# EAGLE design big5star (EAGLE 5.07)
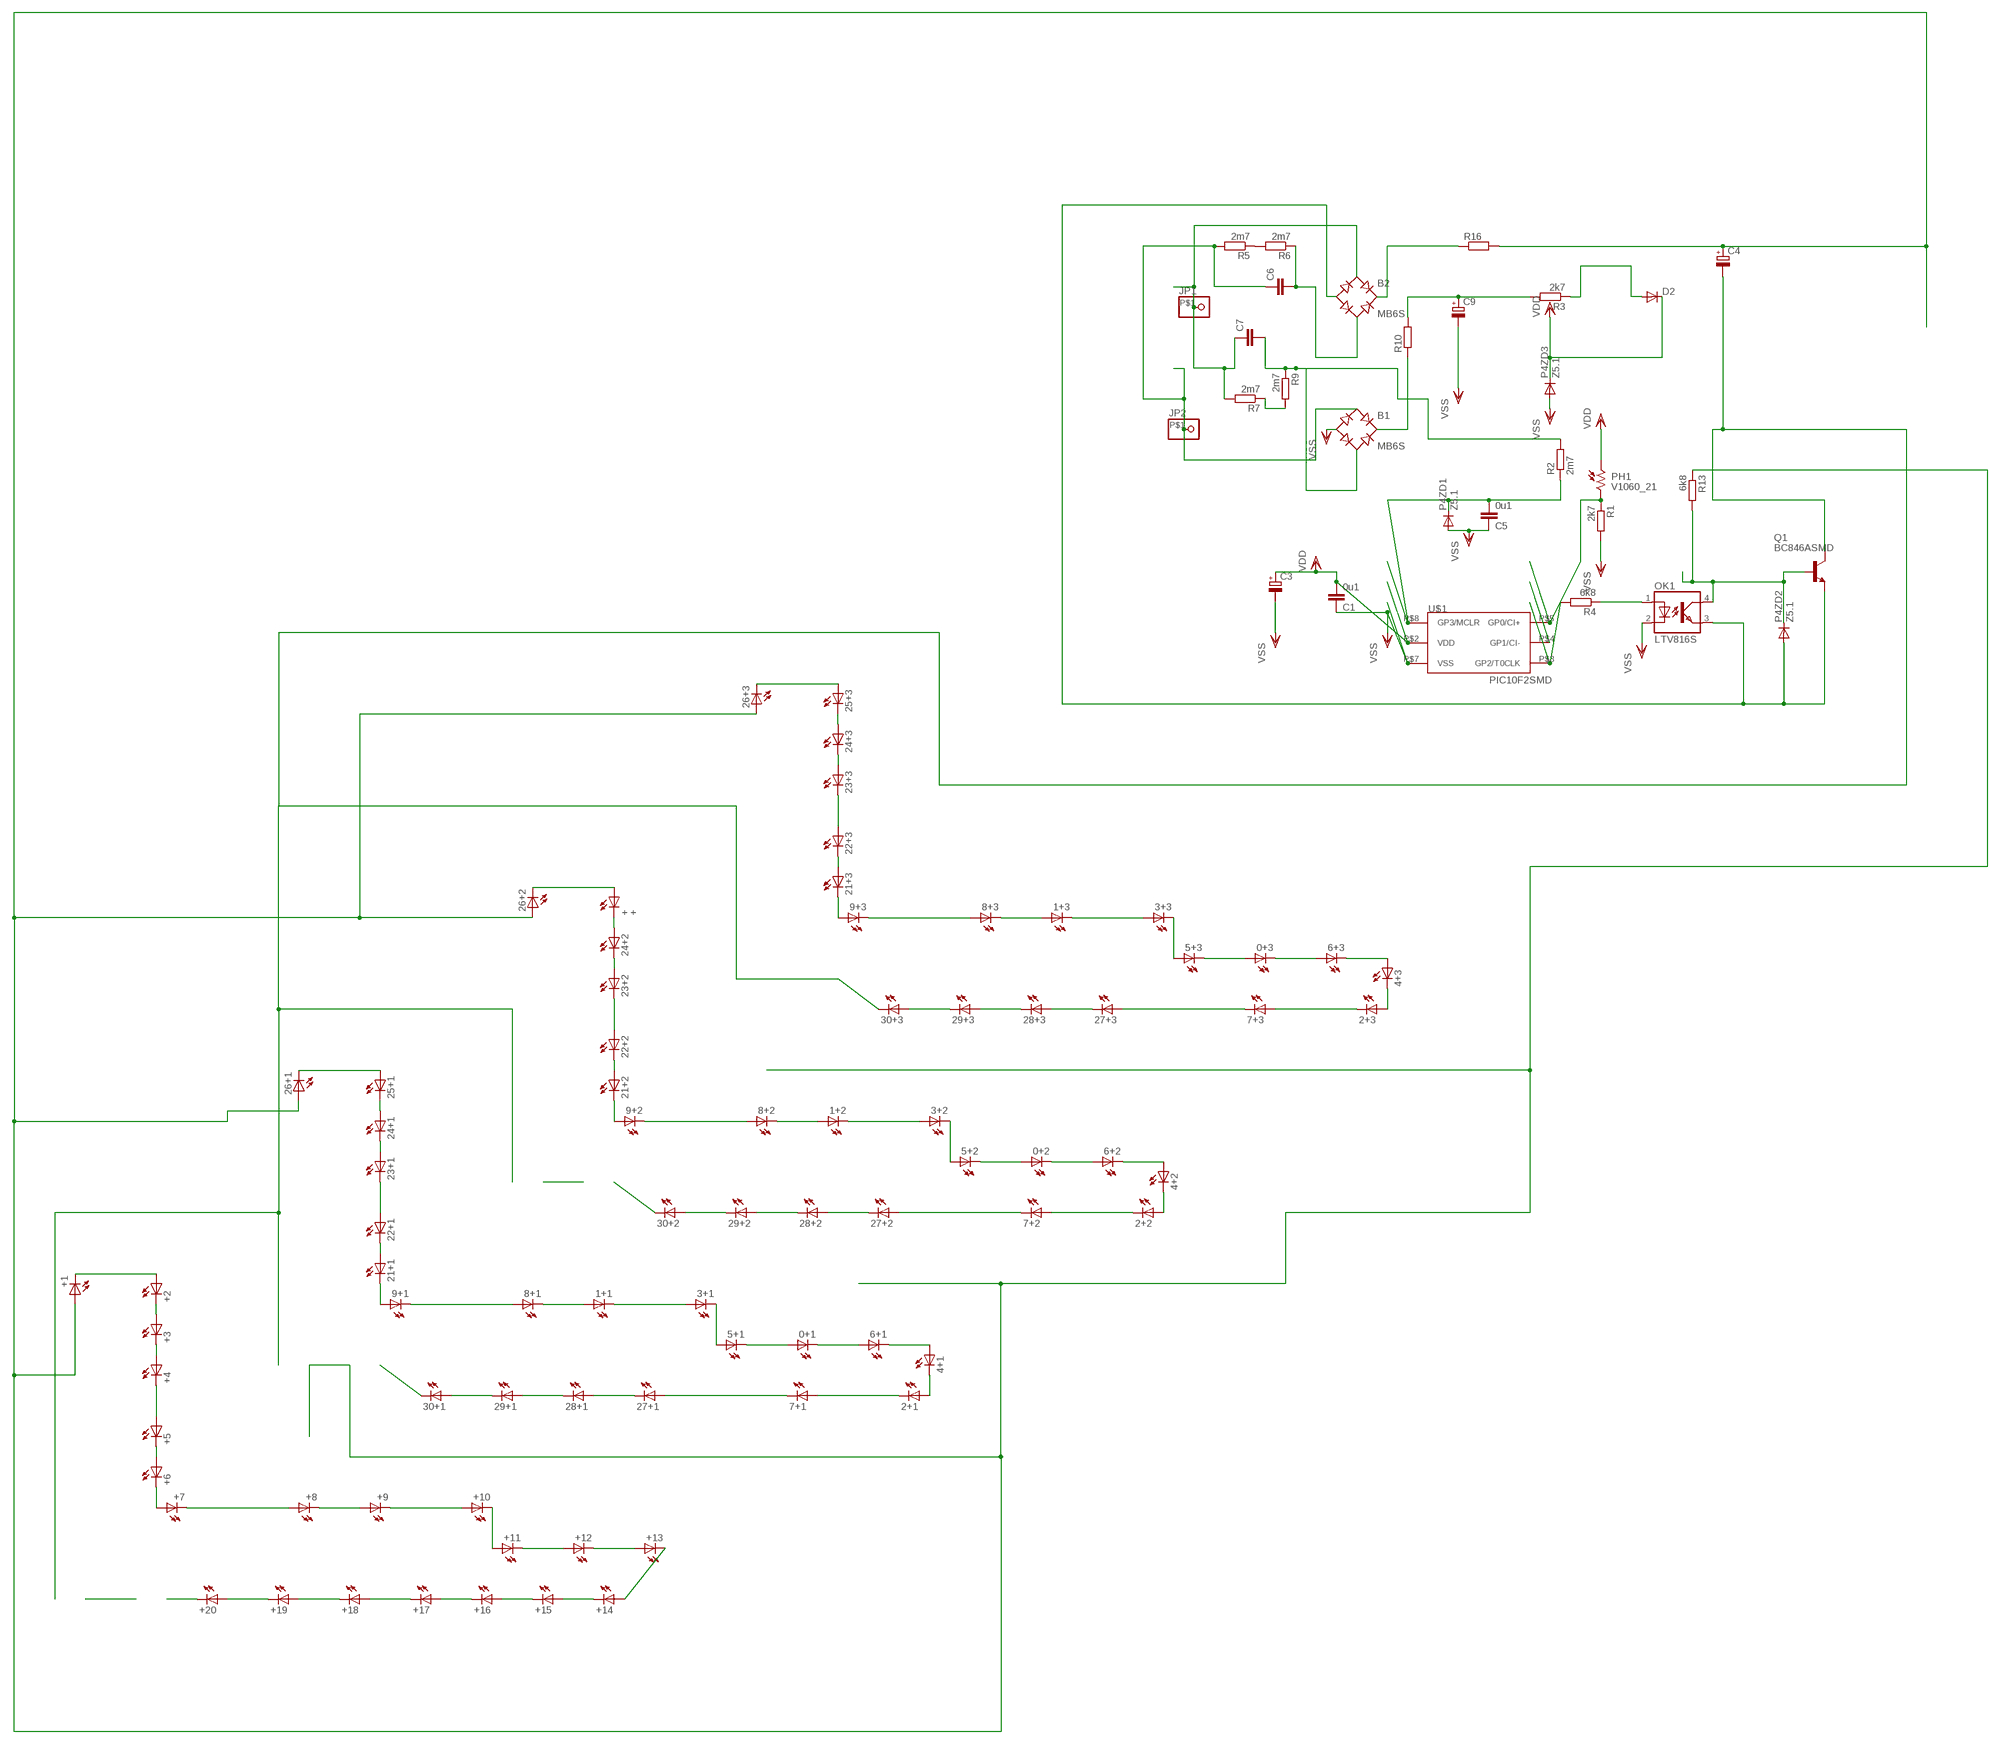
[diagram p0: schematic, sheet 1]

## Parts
0+1  LED1210  [1210]
0+2  LED1210  [1210]
0+3  LED1210  [1210]
1+1  LED1210  [1210]
1+2  LED1210  [1210]
1+3  LED1210  [1210]
2+1  LED1210  [1210]
2+2  LED1210  [1210]
2+3  LED1210  [1210]
3+1  LED1210  [1210]
3+2  LED1210  [1210]
3+3  LED1210  [1210]
4+1  LED1210  [1210]
4+2  LED1210  [1210]
4+3  LED1210  [1210]
5+1  LED1210  [1210]
5+2  LED1210  [1210]
5+3  LED1210  [1210]
6+1  LED1210  [1210]
6+2  LED1210  [1210]
6+3  LED1210  [1210]
7+1  LED1210  [1210]
7+2  LED1210  [1210]
7+3  LED1210  [1210]
8+1  LED1210  [1210]
8+2  LED1210  [1210]
8+3  LED1210  [1210]
9+1  LED1210  [1210]
9+2  LED1210  [1210]
9+3  LED1210  [1210]
21+1  LED1210  [1210]
21+2  LED1210  [1210]
21+3  LED1210  [1210]
22+1  LED1210  [1210]
22+2  LED1210  [1210]
22+3  LED1210  [1210]
23+1  LED1210  [1210]
23+2  LED1210  [1210]
23+3  LED1210  [1210]
24+1  LED1210  [1210]
24+2  LED1210  [1210]
24+3  LED1210  [1210]
25+1  LED1210  [1210]
25+3  LED1210  [1210]
26+1  LED1210  [1210]
26+2  LED1210  [1210]
26+3  LED1210  [1210]
27+1  LED1210  [1210]
27+2  LED1210  [1210]
27+3  LED1210  [1210]
28+1  LED1210  [1210]
28+2  LED1210  [1210]
28+3  LED1210  [1210]
29+1  LED1210  [1210]
29+2  LED1210  [1210]
29+3  LED1210  [1210]
30+1  LED1210  [1210]
30+2  LED1210  [1210]
30+3  LED1210  [1210]
+  +  LED1210  [1210]
+1  LED1210  [1210]
+2  LED1210  [1210]
+3  LED1210  [1210]
+4  LED1210  [1210]
+5  LED1210  [1210]
+6  LED1210  [1210]
+7  LED1210  [1210]
+8  LED1210  [1210]
+9  LED1210  [1210]
+10  LED1210  [1210]
+11  LED1210  [1210]
+12  LED1210  [1210]
+13  LED1210  [1210]
+14  LED1210  [1210]
+15  LED1210  [1210]
+16  LED1210  [1210]
+17  LED1210  [1210]
+18  LED1210  [1210]
+19  LED1210  [1210]
+20  LED1210  [1210]
B1  MB6S  [SOIC-4]
B2  MB6S  [SOIC-4]
C1  0u1  C-EUC1206  [C1206]
C3  CPOL-EUD  [PANASONIC_D]
C4  CPOL-EUSANYO_SMD_F12  [SANYO-OSCON_SMD_F12]
C5  0u1  C-EUC1206  [C1206]
C6  C-EUSMD200  [SMD200]
C7  C-EUSMD100  [SMD100]
C9  CPOL-EUD  [PANASONIC_D]
D2  DIODE-MINIMELF  [MINIMELF]
JP1  PINHD-1X1SMD  [SMD1X1]
JP2  PINHD-1X1SMD  [SMD1X1]
OK1  LTV816S  [SMD4]
P4ZD1  Z5.1  DIODE-MINIMELF  [MINIMELF]
P4ZD2  Z5.1  DIODE-MINIMELF  [MINIMELF]
P4ZD3  Z5.1  DIODE-MINIMELF  [MINIMELF]
PH1  V1060_21  [TO-5_V10]
Q1  BC846ASMD  [SOT23]
R1  2k7  R-EU_R1206  [R1206]
R2  2m7  R-EU_R1206  [R1206]
R3  2k7  R-EU_R1206  [R1206]
R4  6k8  R-EU_R1206  [R1206]
R5  2m7  R-EU_R1210  [R1210]
R6  2m7  R-EU_R1210  [R1210]
R7  2m7  R-EU_R1210  [R1210]
R9  2m7  R-EU_R1210  [R1210]
R10  R-EU_SMD15  [SMDCARB15]
R13  6k8  R-EU_R1206  [R1206]
R16  R-EU_SMD15  [SMDCARB15]
U$1  PIC10F2SMD  [DIL8SMD]

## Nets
AC1: B1.~1(AC1) C6.P$1 JP2.P$1 R5.2
AC2: B2.~1(AC1) C7.P$1 JP1.P$1 R7.2
CBIG: B2.~2(AC2) C6.P$2 R6.1
CSMALL: B1.~2(AC2) C7.P$2 R2.2 R9.1
D+: 26+1.P$1(A) 26+2.P$1(A) 26+3.P$1(A) +1.P$1(A) C4.+ R13.1 R16.P$2
DR+: C9.+ R3.2 R10.P$2
MINUS: 30+3.P$2(C) C4.- Q1.3(C)
N$4: +20.P$2(C)
N$5: 30+1.P$2(C)
N$6: +7.P$2(C) +8.P$1(A)
N$7: +19.P$2(C) +20.P$1(A)
N$8: +18.P$2(C) +19.P$1(A)
N$9: +17.P$2(C) +18.P$1(A)
N$10: 29+1.P$2(C) 30+1.P$1(A)
N$11: 28+1.P$2(C) 29+1.P$1(A)
N$12: +15.P$2(C) +16.P$1(A)
N$13: +16.P$2(C) +17.P$1(A)
N$14: +14.P$2(C) +15.P$1(A)
N$15: +13.P$2(C) +14.P$1(A)
N$16: +12.P$2(C) +13.P$1(A)
N$17: +11.P$2(C) +12.P$1(A)
N$18: +10.P$2(C) +11.P$1(A)
N$19: +9.P$2(C) +10.P$1(A)
N$20: +8.P$2(C) +9.P$1(A)
N$21: 27+1.P$2(C) 28+1.P$1(A)
N$22: 2+1.P$1(A) 4+1.P$2(C)
N$23: +6.P$2(C) +7.P$1(A)
N$24: +5.P$2(C) +6.P$1(A)
N$25: +4.P$2(C) +5.P$1(A)
N$26: +2.P$2(C) +3.P$1(A)
N$27: +1.P$2(C) +2.P$1(A)
N$28: +3.P$2(C) +4.P$1(A)
N$29: 4+1.P$1(A) 6+1.P$2(C)
N$30: 0+1.P$2(C) 6+1.P$1(A)
N$31: 0+1.P$1(A) 5+1.P$2(C)
N$32: 3+1.P$2(C) 5+1.P$1(A)
N$33: 1+1.P$2(C) 3+1.P$1(A)
N$34: 1+1.P$1(A) 8+1.P$2(C)
N$35: 9+1.P$1(A) 21+1.P$2(C)
N$36: 21+1.P$1(A) 22+1.P$2(C)
N$37: 22+1.P$1(A) 23+1.P$2(C)
N$38: 25+1.P$1(A) 26+1.P$2(C)
N$39: 24+1.P$1(A) 25+1.P$2(C)
N$40: 23+1.P$1(A) 24+1.P$2(C)
N$41: 2+1.P$2(C) 7+1.P$1(A)
N$42: 7+1.P$2(C) 27+1.P$1(A)
N$43: 8+1.P$1(A) 9+1.P$2(C)
N$45: 30+2.P$2(C)
N$46: 29+2.P$2(C) 30+2.P$1(A)
N$47: 28+2.P$2(C) 29+2.P$1(A)
N$48: 27+2.P$2(C) 28+2.P$1(A)
N$49: 2+2.P$1(A) 4+2.P$2(C)
N$50: 4+2.P$1(A) 6+2.P$2(C)
N$51: 0+2.P$2(C) 6+2.P$1(A)
N$52: 0+2.P$1(A) 5+2.P$2(C)
N$53: 3+2.P$2(C) 5+2.P$1(A)
N$54: 1+2.P$2(C) 3+2.P$1(A)
N$55: 1+2.P$1(A) 8+2.P$2(C)
N$56: 9+2.P$1(A) 21+2.P$2(C)
N$57: 21+2.P$1(A) 22+2.P$2(C)
N$58: 22+2.P$1(A) 23+2.P$2(C)
N$59: 26+2.P$2(C) +.P$1(A)
N$60: 24+2.P$1(A) +.P$2(C)
N$61: 23+2.P$1(A) 24+2.P$2(C)
N$62: 2+2.P$2(C) 7+2.P$1(A)
N$63: 7+2.P$2(C) 27+2.P$1(A)
N$64: 8+2.P$1(A) 9+2.P$2(C)
N$67: 29+3.P$2(C) 30+3.P$1(A)
N$68: 28+3.P$2(C) 29+3.P$1(A)
N$69: 27+3.P$2(C) 28+3.P$1(A)
N$70: 2+3.P$1(A) 4+3.P$2(C)
N$71: 4+3.P$1(A) 6+3.P$2(C)
N$72: 0+3.P$2(C) 6+3.P$1(A)
N$73: 0+3.P$1(A) 5+3.P$2(C)
N$74: 3+3.P$2(C) 5+3.P$1(A)
N$75: 1+3.P$2(C) 3+3.P$1(A)
N$76: 1+3.P$1(A) 8+3.P$2(C)
N$77: 9+3.P$1(A) 21+3.P$2(C)
N$78: 21+3.P$1(A) 22+3.P$2(C)
N$79: 22+3.P$1(A) 23+3.P$2(C)
N$80: 25+3.P$1(A) 26+3.P$2(C)
N$81: 24+3.P$1(A) 25+3.P$2(C)
N$82: 23+3.P$1(A) 24+3.P$2(C)
N$83: 2+3.P$2(C) 7+3.P$1(A)
N$84: 7+3.P$2(C) 27+3.P$1(A)
N$85: 8+3.P$1(A) 9+3.P$2(C)
N$86: C5.2 P4ZD1.C R2.1 U$1.P$8(GP3/MCLR)
N$87: OK1.1(A) R4.1
N$88: PH1.2 R1.1 U$1.P$5(GP0/CI+)
N$89: R5.1 R6.2
N$90: R7.1 R9.2
N$91: B2.+ R16.P$1
N$92: D2.A R3.1
N$93: B2.- OK1.3(EMIT) P4ZD2.A Q1.2(E)
N$94: OK1.4(COL) P4ZD2.C Q1.1(B) R13.2
N$95: R4.2 U$1.P$3(GP2/T0CLK)
N$102: U$1.P$4(GP1/CI-)
RECDR+: B1.+ R10.P$1
VDD: C1.2 C3.+ D2.C P4ZD3.C PH1.1 U$1.P$2(VDD)
VSS: B1.- C1.1 C3.- C5.1 C9.- OK1.2(C) P4ZD1.A P4ZD3.A R1.2 U$1.P$7(VSS)

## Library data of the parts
0+1-0+3 1+1-1+3 2+1-2+3 3+1-3+3 4+1-4+3 5+1-5+3 6+1-6+3 7+1-7+3 8+1-8+3 9+1-9+3 21+1-21+3 22+1-22+3 23+1-23+3 24+1-24+3 25+1 25+3 26+1-26+3 27+1-27+3 28+1-28+3 29+1-29+3 30+1-30+3 + +1-+20 = led(2):LED: LED
B1 B2 = rectifier:MB*S: Bridge Rectifier Source: http://www.fairchildsemi.com/ds/MB/MB6S.pdf
C1 C5-C7 = rcl:C-EU: CAPACITOR, European symbol
C3 C4 C9 = rcl-2:CPOL-EU: POLARIZED CAPACITOR, European symbol
D2 P4ZD1-P4ZD3 = diode:DIODE-: DIODE
JP1 JP2 = pinhead:PINHD-1X1: PIN HEADER
OK1 = optocoupler:LTV816: OPTO COUPLER Source: LITEON, LTV816.pdf
PH1 = photo-elements:?1060*: Sensor Street Light control
Q1 = transistor-npn:BC846*: NPN Transistor
R1-R7 R9 R13 = rcl-2:R-EU_: RESISTOR, European symbol
R10 R16 = rcl:R-EU_: RESISTOR, European symbol
U$1 = microchip-5:PIC10F2*: uPC nW 0,25/0,5k Program Flash memory Comparator

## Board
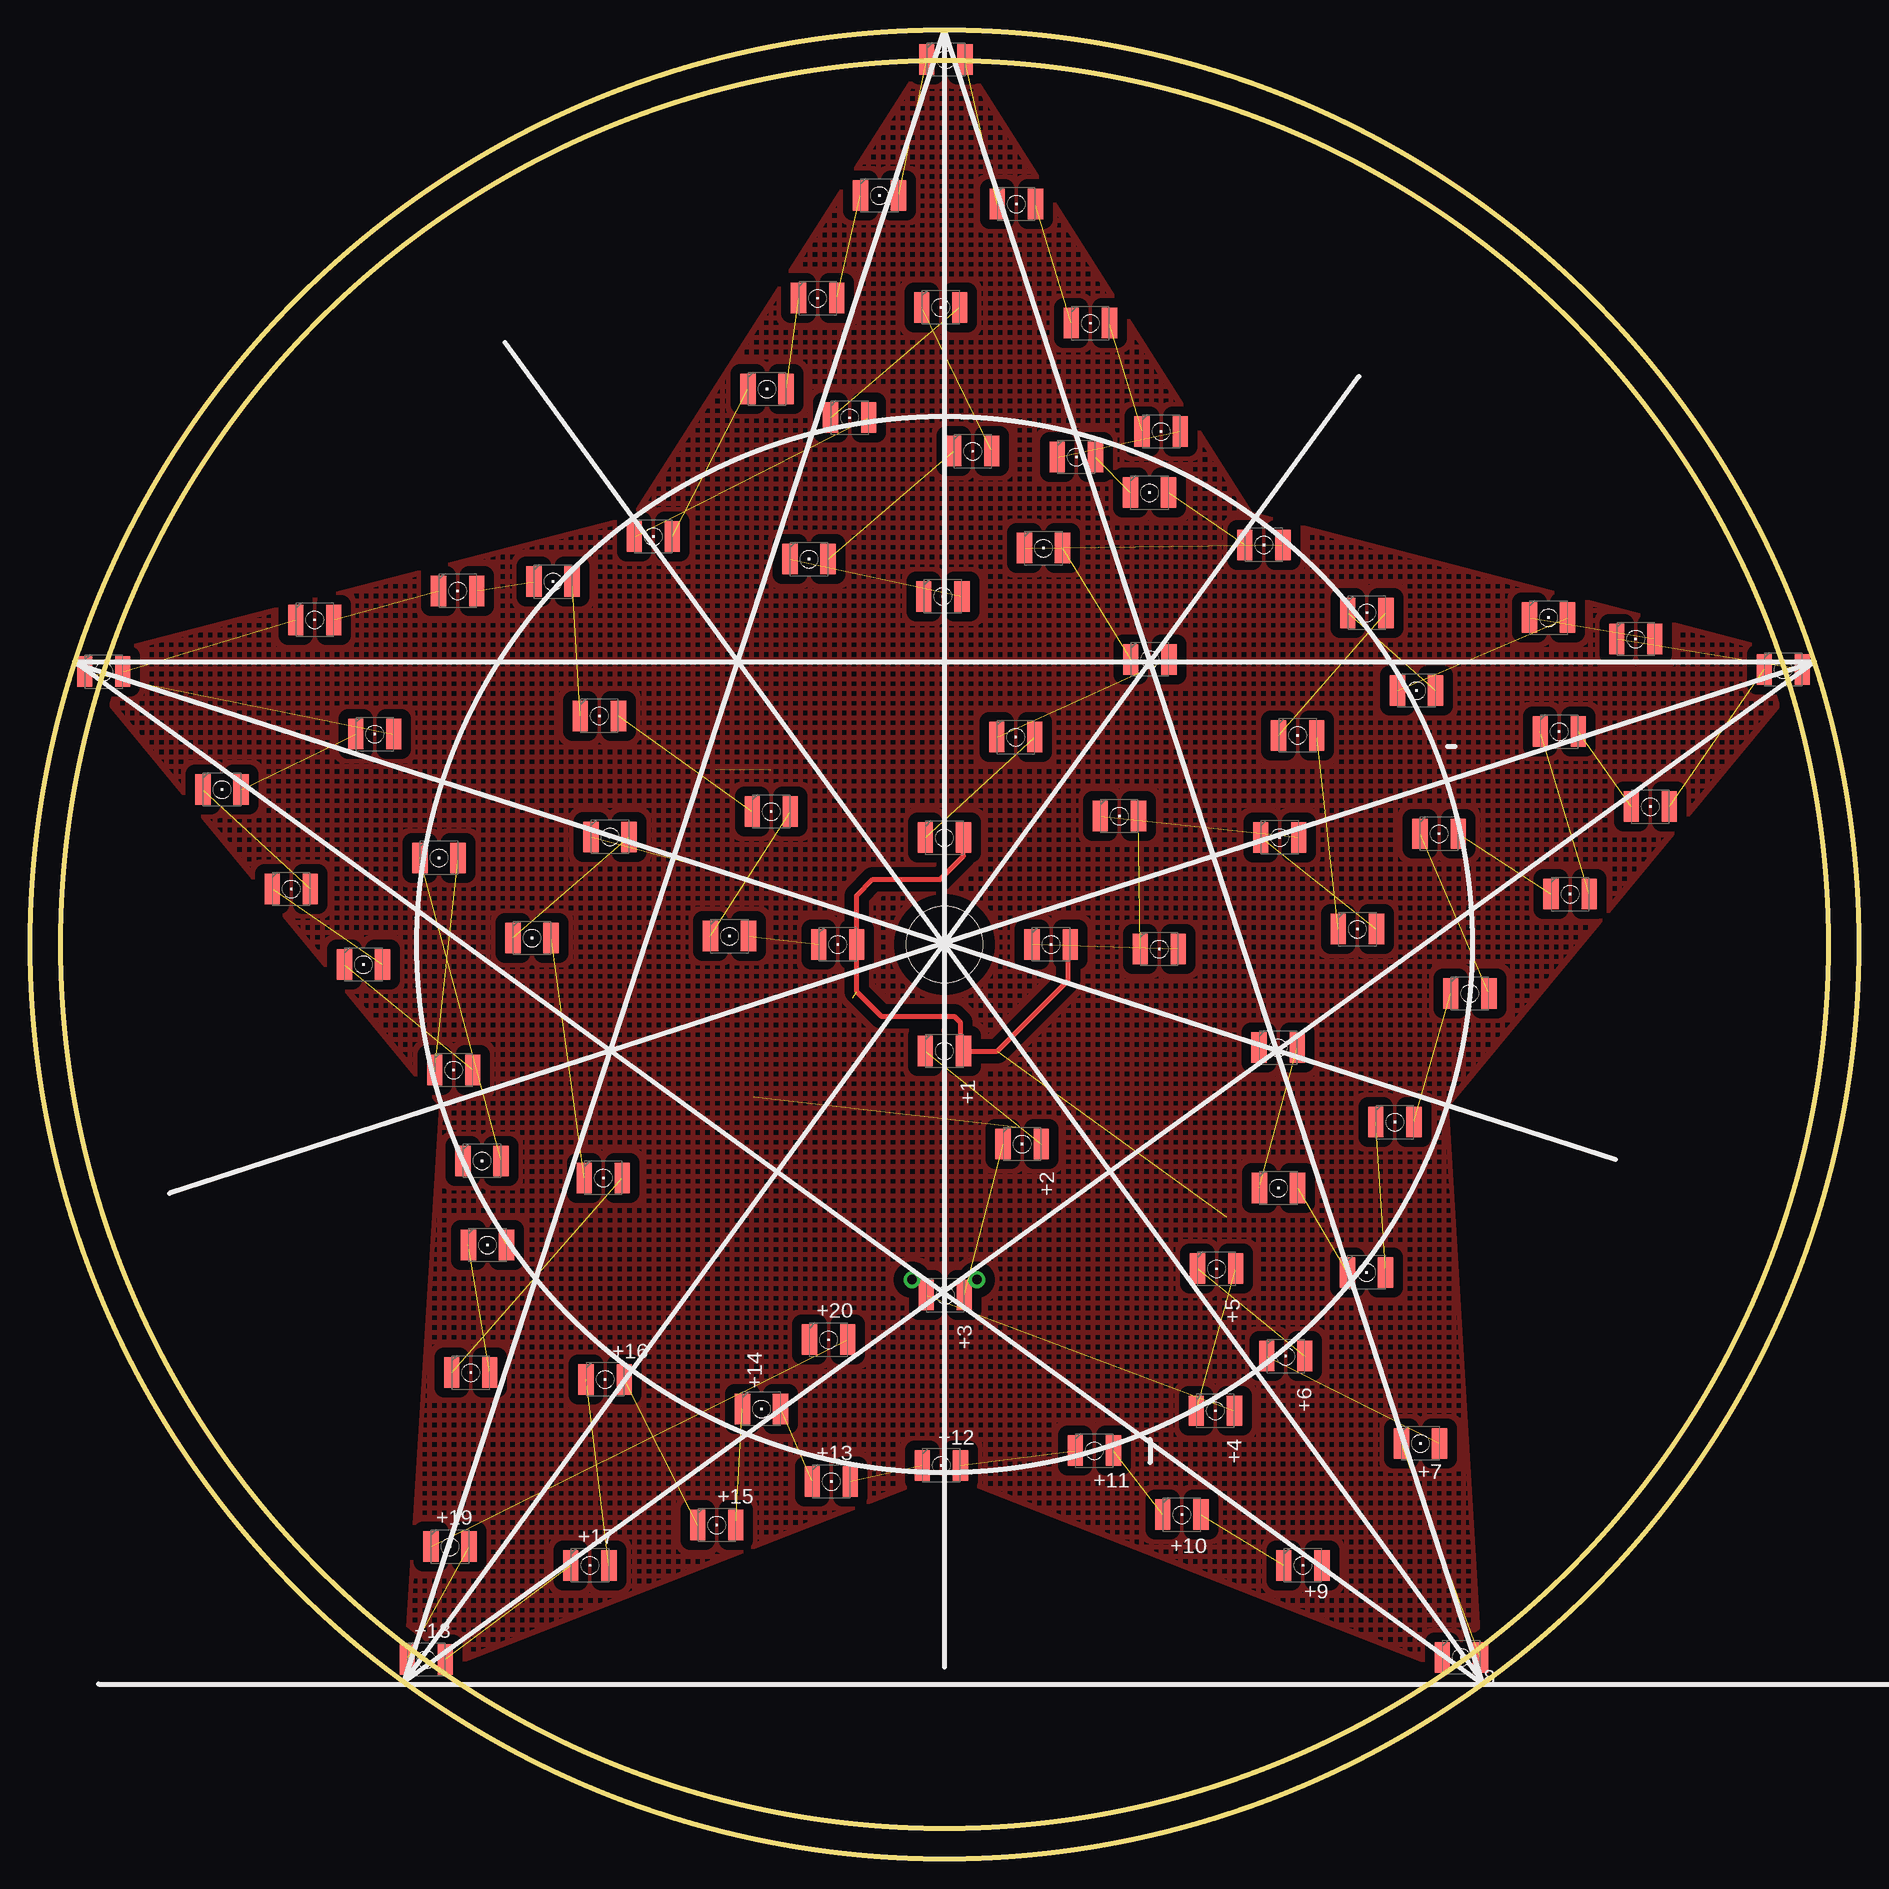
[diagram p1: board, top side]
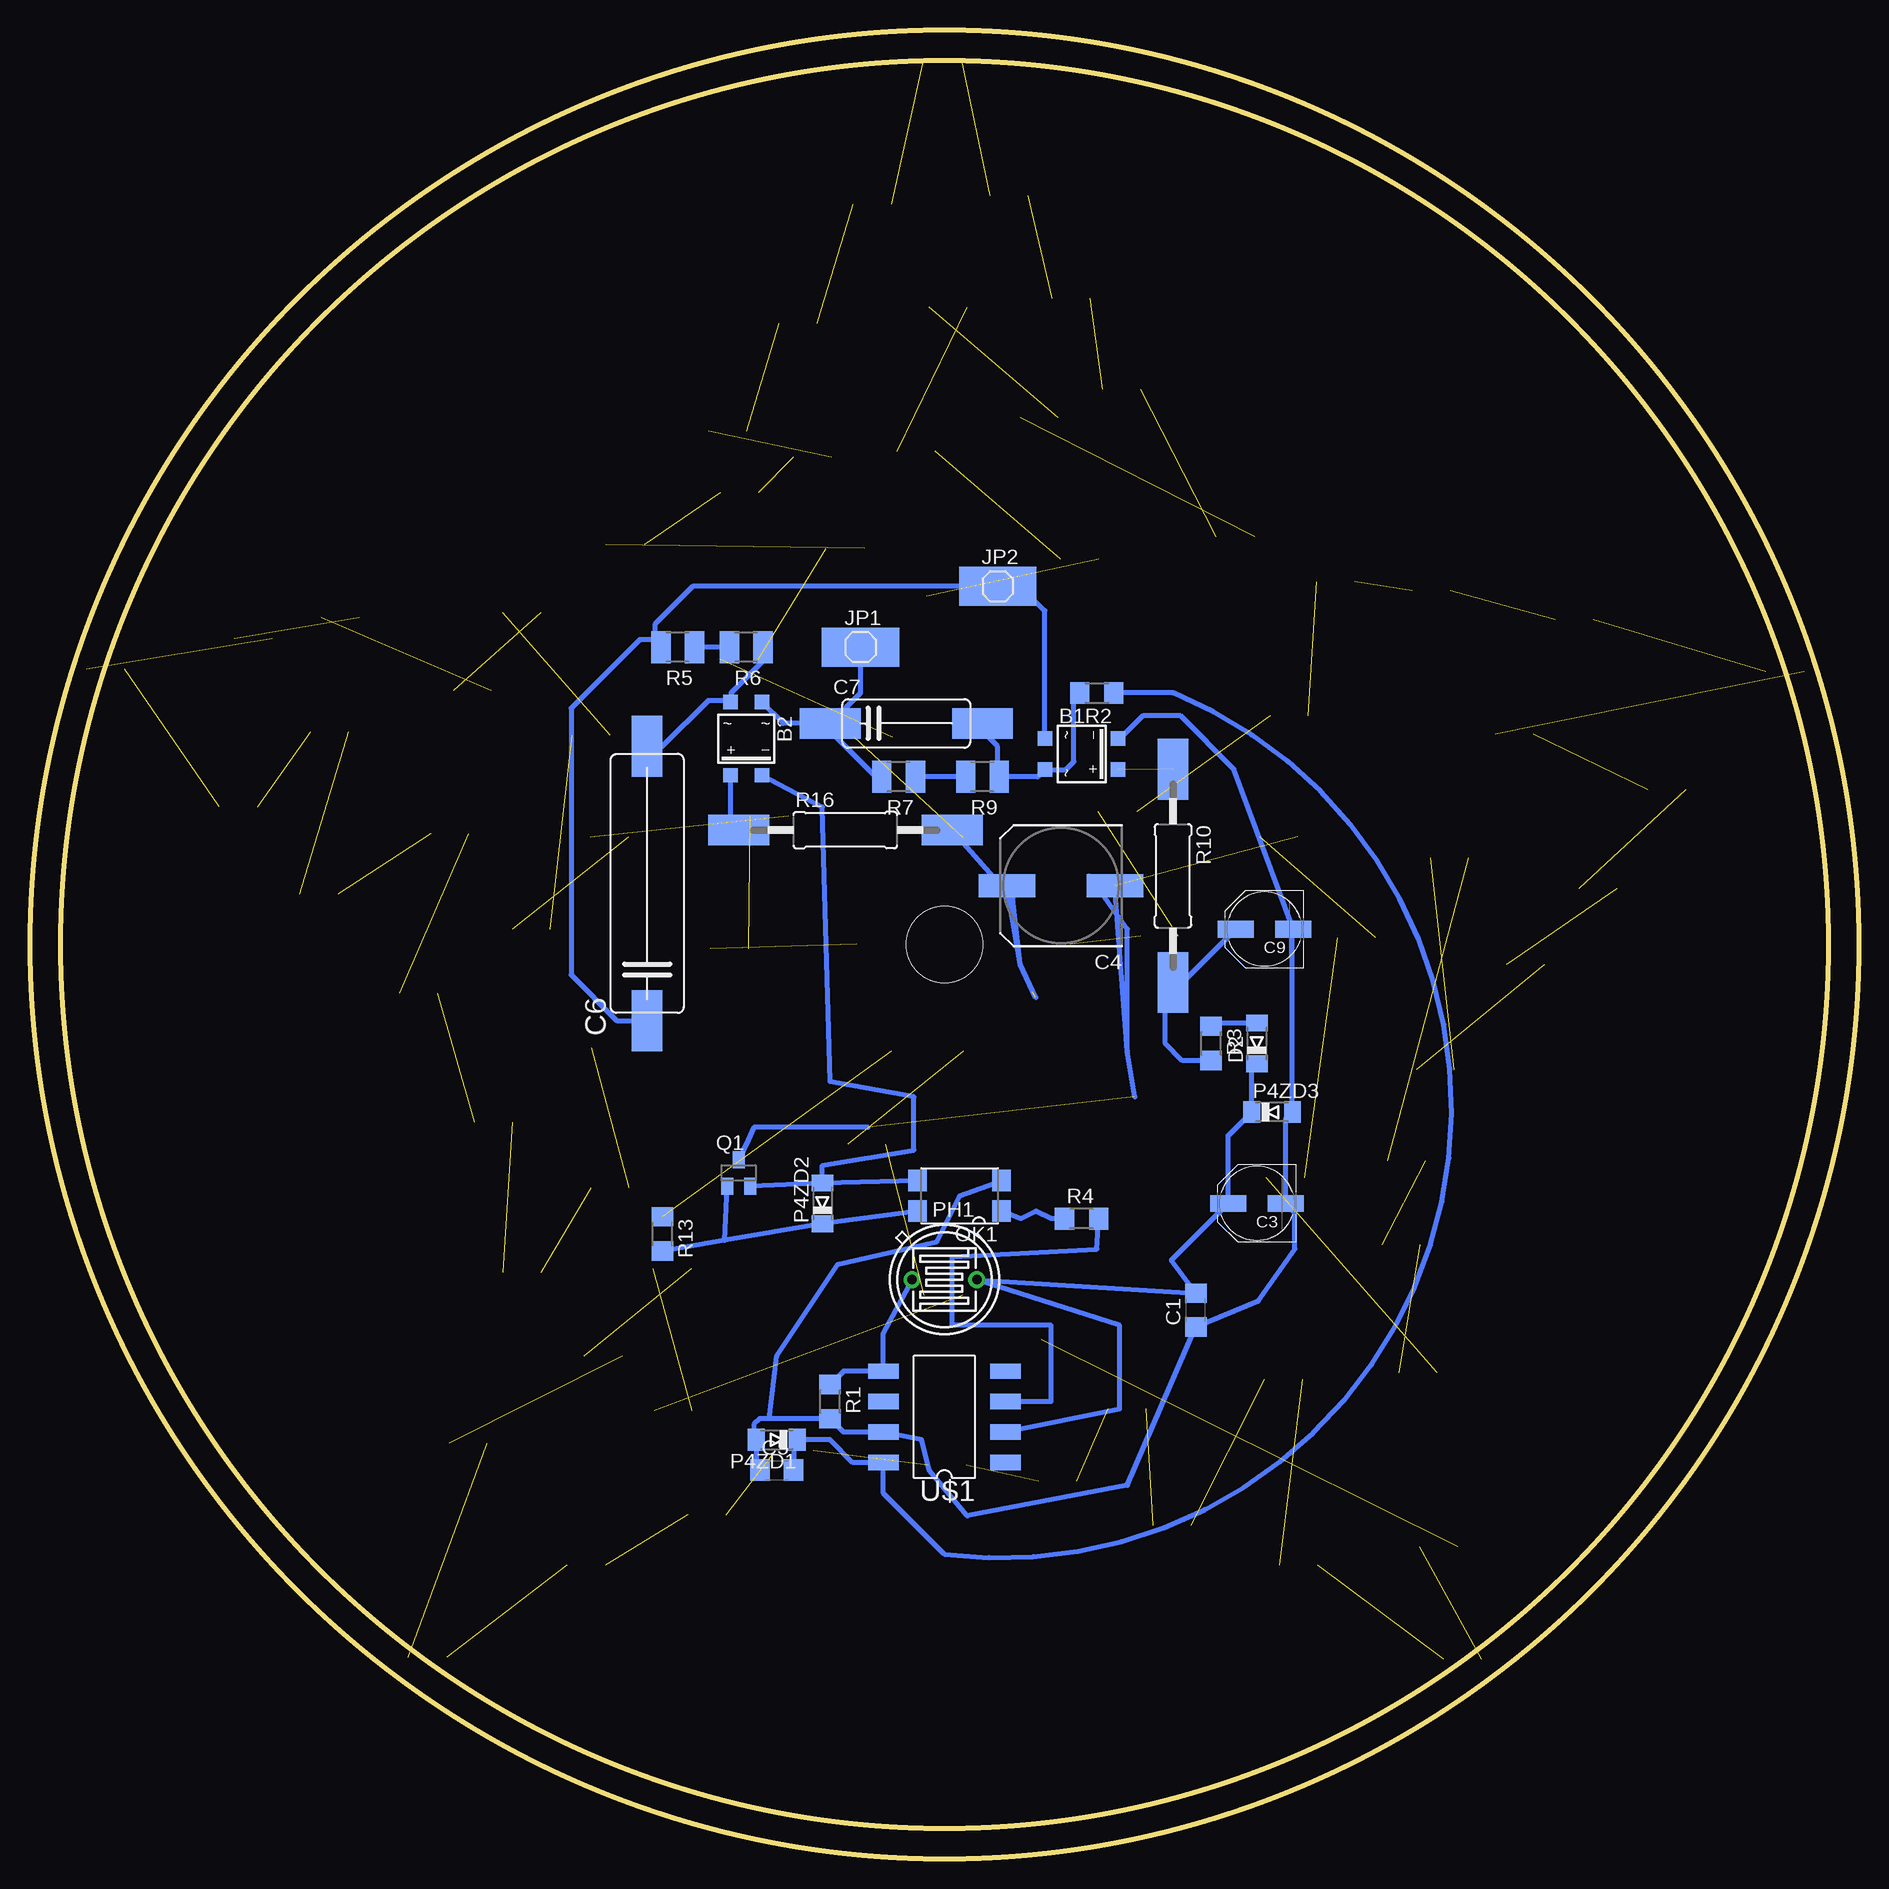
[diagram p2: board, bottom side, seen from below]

Size 152.4 x 152.4 mm. Coordinates in mm from the lower left corner, seen from the top.
Outline: circle at 76.2,76.2 radius 76.2
Outline: circle at 76.2,76.2 radius 73.66
Copper layers (1*16): Top 0.035mm / dielectric 1.5mm / Bottom 0.035mm
Design rules "default": minimum track width 10mil, minimum drill 24mil, track to track 8mil, track to pad 8mil, pad to pad 8mil, via to via 8mil, smd to smd 8mil, copper to edge 40mil, drill to drill 8mil, minimum pad ring 10mil, minimum via ring 8mil, stop-mask expansion 4mil, vias tented up to drill 0mil, thermal gap 10mil
Holes 6.35 mm at 76.2,76.2

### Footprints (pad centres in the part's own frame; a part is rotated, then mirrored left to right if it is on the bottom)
1210 = smd 1.27 x 2.54: P$1 1.587,0; P$2 -1.587,0
SOIC-4 = smd 1.2 x 1.2: + 1.3,3.05; - -1.3,3.05; ~1 -1.3,-3.05; ~2 1.3,-3.05
C1206 = smd 1.6 x 1.8: 1 -1.4,0; 2 1.4,0
PANASONIC_D = smd 3 x 1.4: + 2.4,0; - -2.4,0
SANYO-OSCON_SMD_F12 = smd 4.7 x 1.9: + 4.5,0; - -4.5,0
SMD200 = smd 5.08 x 2.54: P$1 -10.16,0; P$2 12.7,0
SMD100 = smd 5.08 x 2.54: P$1 -6.35,0; P$2 6.35,0
MINIMELF = smd 1.4 x 1.8: A 1.7,0; C -1.7,0
SMD1X1 = smd 6.452 x 3.251: P$1 0,0
SMD4 = smd 1.78 x 1.55: 1 -1.27,-3.5; 2 1.27,-3.5; 3 1.27,3.5; 4 -1.27,3.5
TO-5_V10 = drill 0.8 pad 1.4 round: 1 -2.7,0; 2 2.7,0
SOT23 = smd 1 x 1.4: 1 -0.95,-1.1; 2 0.95,-1.1; 3 0,1.1
R1206 = smd 1.6 x 1.803: 1 -1.422,0; 2 1.422,0
R1210 = smd 1.6 x 2.7: 1 -1.4,0; 2 1.4,0
SMDCARB15 = smd 5.08 x 2.54: P$1 -8.89,0; P$2 8.89,0
DIL8SMD = smd 1.27 x 2.54: P$1 -3.81,-5.08; P$2 -1.27,-5.08; P$3 1.27,-5.08; P$4 3.81,-5.08; P$5 3.81,5.08; P$6 1.27,5.08; P$7 -1.27,5.08; P$8 -3.81,5.08

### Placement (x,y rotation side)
0+1  135.03,87.68 0 top
0+2  70.79,138.61 0 top
0+3  27.79,74.52 0 top
1+1  126.54,103.43 0 top
1+2  88.37,127.97 0 top
1+3  28.73,93.73 0 top
2+1  117.42,85.42 0 top
2+2  51.94,110.19 0 top
2+3  37.67,58.17 0 top
3+1  133.81,101.65 0 top
3+2  82.19,137.9 0 top
3+3  16,89.1 0 top
4+1  128.35,80.39 0 top
4+2  61.42,122.48 0 top
4+3  34.09,83.41 0 top
5+1  146.1,99.11 0 top
5+2  76.33,149.94 0 top
5+3  21.77,80.82 0 top
6+1  127.43,93.93 0 top
6+2  65.63,130.05 0 top
6+3  35.31,65.74 0 top
7+1  119.99,72.11 0 top
7+2  68.3,120.09 0 top
7+3  38.13,51.16 0 top
8+1  115.54,97.36 0 top
8+2  94.26,118.95 0 top
8+3  6.15,98.93 0 top
9+1  111.4,103.84 0 top
9+2  87.2,116.81 0 top
9+3  23.72,103.25 0 top
21+1  105.64,93.62 0 top
21+2  93.29,113.84 0 top
21+3  35.64,105.66 0 top
22+1  110.62,77.47 0 top
22+2  102.82,109.5 0 top
22+3  43.59,106.43 0 top
23+1  104.14,85.12 0 top
23+2  84.45,109.22 0 top
23+3  47.45,95.25 0 top
24+1  90.78,86.89 0 top
24+2  93.32,99.95 0 top
24+3  61.77,87.27 0 top
25+1  94.11,75.82 0 top
25+3  58.29,76.89 0 top
26+1  85.09,76.2 0 top
26+2  76.2,85.09 0 top
26+3  67.31,76.2 0 top
27+1  113.74,61.39 0 top
27+2  75.9,129.29 0 top
27+3  36.73,40.51 0 top
28+1  111.38,48.87 0 top
28+2  78.56,117.3 0 top
28+3  47.78,56.74 0 top
29+1  104.04,55.91 0 top
29+2  64.92,108.31 0 top
29+3  41.83,76.73 0 top
30+1  104.01,67.59 0 top
30+2  76.07,105.21 0 top
30+3  48.34,85.17 0 top
+  82.14,93.47 0 top
+1  76.2,67.31 0 top
+2  82.68,59.56 0 top
+3  76.28,46.96 0 top
+4  98.78,37.34 0 top
+5  98.88,49.17 0 top
+6  104.65,41.88 0 top
+7  115.87,34.62 0 top
+8  119.28,16.79 0 top
+9  106.07,24.46 0 top
+10  95.99,28.68 0 top
+11  88.7,34.01 0 top
+12  75.95,32.79 0 top
+13  66.78,31.45 0 top
+14  60.96,37.49 0 top
+15  57.23,27.81 0 top
+16  47.93,39.95 0 top
+17  46.66,24.46 0 top
+18  33.02,16.61 0 top
+19  35,26.01 0 top
+20  66.55,43.26 0 top
B1  64.77,92.08 270 bottom
B2  92.71,93.34 180 bottom
C1  55.24,45.72 90 bottom
C3  50.16,54.61 180 bottom
C4  66.49,81.09 180 bottom
C5  90.17,32.38 0 bottom
C6  100.97,80.01 90 bottom
C7  79.38,94.61 0 bottom
C9  49.53,77.47 180 bottom
D2  50.16,67.94 90 bottom
JP1  83.19,100.97 0 bottom
JP2  71.75,106.05 0 bottom
OK1  74.93,55.24 90 bottom
P4ZD1  90.17,34.92 180 bottom
P4ZD2  86.36,54.61 90 bottom
P4ZD3  48.9,62.23 0 bottom
PH1  76.2,48.26 180 bottom
Q1  93.34,57.15 0 bottom
R1  85.72,38.1 270 bottom
R2  63.5,97.16 180 bottom
R3  53.98,67.94 270 bottom
R4  64.77,53.34 0 bottom
R5  98.42,100.97 180 bottom
R6  92.71,100.97 180 bottom
R7  80.01,90.17 180 bottom
R9  73.03,90.17 180 bottom
R10  57.15,81.92 270 bottom
R13  99.69,52.07 270 bottom
R16  84.45,85.72 0 bottom
U$1  76.2,36.83 90 bottom

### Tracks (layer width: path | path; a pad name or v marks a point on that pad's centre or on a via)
AC1
  Bottom 0.406: B1.~1 67.82,104.02 69.85,106.05 JP2.P$1 97.16,106.05 100.33,102.87 100.33,101.6 | 100.33,101.6 100.33,101.47 R5.2 | C6.P$1 103.5,69.85 107.31,73.66 107.31,95.89 101.6,101.6 100.33,101.6
AC2
  Bottom 0.406: R7.2 81.92,90.17 86.36,94.61 C7.P$1 | JP1.P$1 83.19,97.16 C7.P$1 | C7.P$1 89.63,94.61 B2.~1
CBIG
  Bottom 0.406: R6.1 91.31,99.83 93.98,97.16 93.98,96.42 B2.~2 94.14,96.52 95.89,96.52 99.69,92.71 C6.P$2
CSMALL
  Bottom 0.406: R2.2 65.41,96.67 65.41,91.44 66.07,90.78 B1.~2 68.42,90.17 R9.1 71.75,90.3 71.75,92.71 73.03,93.98 C7.P$2
D+  (2 unrouted)
  Top 0.406: 26+1.P$1 86.51,76.03 86.51,73.2 80.62,67.31 +1.P$1 77.52,67.58 77.52,69.72 77.04,70.21 70.94,70.21 68.9,72.25 26+3.P$1 68.89,76.21 68.89,80.26 70.23,81.61 75.84,81.61 77.79,83.55 26+2.P$1
  Bottom 0.406: 69.87,74.53 C4.+ | 69.87,74.53 70.48,80.01 R16.P$2 | 68.58,71.75 69.87,74.53
DR+
  Bottom 0.406: R3.2 56.36,66.52 57.78,67.94 57.78,72.39 R10.P$2 56.38,73.03 C9.+
MINUS  (2 unrouted)
  Bottom 0.406: 64.14,81.92 60.96,77.47 60.96,67.31 | 60.96,67.31 C4.- | 60.33,63.5 60.96,67.31 | 82.55,60.96 92.08,60.96 92.56,59.92 Q1.3
N$3
  pour Top (isolate 0.813, hatched): 34.26,62.74 31.24,14.66 76.15,32.23 120.95,14.66 118.06,62.71 148.74,99.77 101.78,112.06 76.2,152.4 50.22,111.73 3.76,99.75
N$6  (1 unrouted)
N$7  (1 unrouted)
N$8  (1 unrouted)
N$9  (1 unrouted)
N$10  (1 unrouted)
N$11  (1 unrouted)
N$12  (1 unrouted)
N$13  (1 unrouted)
N$14  (1 unrouted)
N$15  (1 unrouted)
N$16  (1 unrouted)
N$17  (1 unrouted)
N$18  (1 unrouted)
N$19  (1 unrouted)
N$20  (1 unrouted)
N$21  (1 unrouted)
N$22  (1 unrouted)
N$23  (1 unrouted)
N$24  (1 unrouted)
N$25  (1 unrouted)
N$26  (1 unrouted)
N$27  (1 unrouted)
N$28  (1 unrouted)
N$29  (1 unrouted)
N$30  (1 unrouted)
N$31  (1 unrouted)
N$32  (1 unrouted)
N$33  (1 unrouted)
N$34  (1 unrouted)
N$35  (1 unrouted)
N$36  (1 unrouted)
N$37  (1 unrouted)
N$38  (1 unrouted)
N$39  (1 unrouted)
N$40  (1 unrouted)
N$41  (1 unrouted)
N$42  (1 unrouted)
N$43  (1 unrouted)
N$46  (1 unrouted)
N$47  (1 unrouted)
N$48  (1 unrouted)
N$49  (1 unrouted)
N$50  (1 unrouted)
N$51  (1 unrouted)
N$52  (1 unrouted)
N$53  (1 unrouted)
N$54  (1 unrouted)
N$55  (1 unrouted)
N$56  (1 unrouted)
N$57  (1 unrouted)
N$58  (1 unrouted)
N$59  (1 unrouted)
N$60  (1 unrouted)
N$61  (1 unrouted)
N$62  (1 unrouted)
N$63  (1 unrouted)
N$64  (1 unrouted)
N$67  (1 unrouted)
N$68  (1 unrouted)
N$69  (1 unrouted)
N$70  (1 unrouted)
N$71  (1 unrouted)
N$72  (1 unrouted)
N$73  (1 unrouted)
N$74  (1 unrouted)
N$75  (1 unrouted)
N$76  (1 unrouted)
N$77  (1 unrouted)
N$78  (1 unrouted)
N$79  (1 unrouted)
N$80  (1 unrouted)
N$81  (1 unrouted)
N$82  (1 unrouted)
N$83  (1 unrouted)
N$84  (1 unrouted)
N$85  (1 unrouted)
N$86
  Bottom 0.406: R2.1 57.15,97.16 arc165 76.2,25.4 81.28,30.48 U$1.P$8 83.82,33.02 85.72,34.92 P4ZD1.C 88.77,34.62 C5.2
N$87
  Bottom 0.406: R4.1 67.31,53.34 68.58,53.98 69.85,53.34 OK1.1
N$88
  Bottom 0.406: R1.1 84.61,40.64 U$1.P$5 81.28,43.81 PH1.2
N$89
  Bottom 0.406: R6.2 96.52,100.97 97.16,100.33 97.16,100.83 R5.1
N$90
  Bottom 0.406: R9.2 R7.1
N$91
  Bottom 0.406: B2.+ 94.01,86.39 R16.P$1
N$92
  Bottom 0.406: D2.A 53.7,69.64 R3.1
N$93
  Bottom 0.406: B2.- 86.36,87.63 85.72,64.77 78.74,63.5 78.74,59.05 86.36,57.78 P4ZD2.A | P4ZD2.A Q1.2 | OK1.3 P4ZD2.A
N$94
  Bottom 0.406: OK1.4 P4ZD2.C 94.52,51.52 | 94.52,51.52 R13.2 | 94.52,51.52 Q1.1
N$95
  Bottom 0.406: U$1.P$3 67.31,38.1 67.31,44.45 75.56,44.45 75.56,50.16 63.5,50.8 R4.2
RECDR+  (1 unrouted)
VDD
  Bottom 0.406: D2.C 50.59,65.81 P4ZD3.C 52.56,60.26 C3.+ 57.28,49.9 C1.2 PH1.1 61.59,44.45 61.59,37.47 U$1.P$2
VSS
  Bottom 0.406: 90.81,36.68 R1.2 84.61,35.56 U$1.P$7 78.11,34.92 77.47,32.38 74.3,28.57 60.96,31.11 C1.1 50.03,46.48 46.99,50.8 46.99,53.84 C3.- 47.77,61.66 P4ZD3.A 47.2,77.41 C9.- 52.07,90.81 56.52,95.25 59.69,95.25 61.56,93.38 B1.- | 90.81,36.68 91.59,36.68 92.08,36.2 92.08,35.13 P4ZD1.A 91.87,33.23 92.08,33.02 92.08,32.89 C5.1 | OK1.2 74.93,55.24 76.83,51.44 85.09,49.53 90.17,41.91 90.81,36.68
